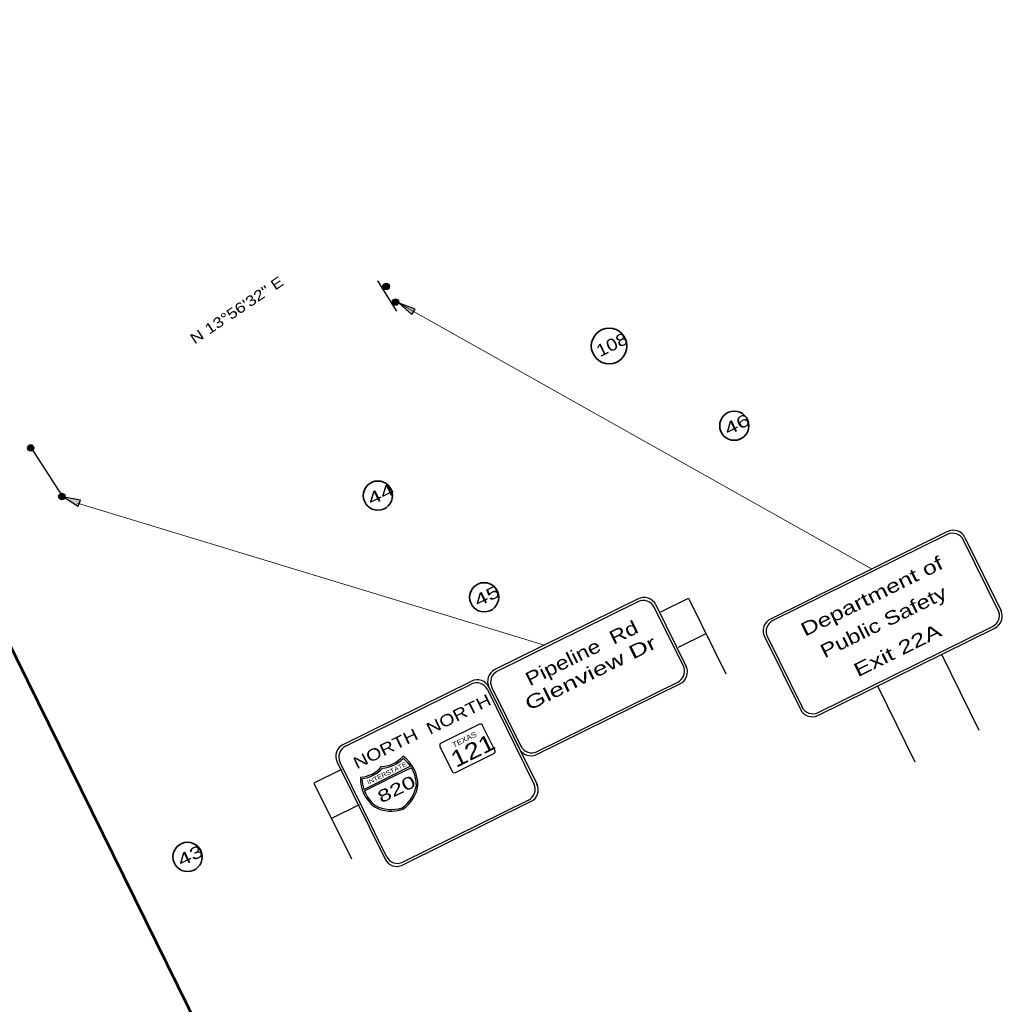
# Model space of a CAD drawing. Extents: x 2356431 to 2371438, y 6972864 to 6982525.
# Drawn here: x 2365828 to 2366960, y 6978894 to 6980028 of the extents above; entities that cross this region are included whole.
import ezdxf
from ezdxf.enums import TextEntityAlignment as Align

# ---------------------------------------------------------------- set-up
doc = ezdxf.new("R2010")
doc.units = 0
doc.header["$LTSCALE"] = 5.6
for name, color, linetype, lineweight in [('1', 7, 'Continuous', 25), ('17', 7, 'Continuous', 35), ('28', 7, 'Continuous', 35)]:
    doc.layers.add(name, color=color, linetype=linetype, lineweight=lineweight)

msp = doc.modelspace()

# ---------------------------------------------------------------- hatches: boundary and pattern name
at = {"layer": '1'}
for points in [[(2366246.217, 6979721.254, 1), (2366253.662, 6979720.728, 1)], [(2366257.128, 6979703.235, 1), (2366264.573, 6979702.71, 1)], [(2366264.891, 6979701.538), (2366279.644, 6979688.739), (2366283.284, 6979694.954)], [(2365843.964, 6979535.242, 1), (2365836.537, 6979534.506, 1)], [(2365880.035, 6979479.344, 1), (2365872.608, 6979478.608, 1)], [(2365878.551, 6979478.108), (2365895.163, 6979467.836), (2365897.761, 6979474.553)]]:
    msp.add_hatch(color=256, dxfattribs=at).paths.add_polyline_path(points)

# ---------------------------------------------------------------- linework, layer by layer
at = {"layer": '1', "lineweight": 53}
msp.add_line((2365274.698, 6980404.566), (2366089.834, 6978752.959), dxfattribs=at)
at = {"layer": '1'}
for p, q in [((2366262.128, 6979692.544), (2366240.48, 6979727.603)), ((2365840.38, 6979535.416), (2365876.764, 6979478.712)), ((2366897.034, 6979438.449), (2366692.9, 6979337.61)), ((2366896.596, 6979435.087), (2366695.833, 6979335.925)), ((2366956.339, 6979345.964), (2366915.485, 6979428.681)), ((2366917.183, 6979431.624), (2366958.818, 6979347.331)), ((2366540.586, 6979360.951), (2366375.359, 6979279.406)), ((2366566.679, 6979346.051), (2366598.565, 6979361.789)), ((2366598.565, 6979361.789), (2366641.672, 6979274.445)), ((2366540.145, 6979357.592), (2366378.29, 6979277.721)), ((2366593.335, 6979281.658), (2366559.029, 6979351.179)), ((2366560.728, 6979354.12), (2366595.814, 6979283.024)), ((2366747.442, 6979226.514), (2366951.569, 6979327.35)), ((2366748.15, 6979230.012), (2366949.078, 6979329.264)), ((2366586.822, 6979305.245), (2366618.706, 6979320.98)), ((2366686.065, 6979317.456), (2366727.421, 6979233.728)), ((2366689.436, 6979317.015), (2366729.423, 6979236.057)), ((2366890.217, 6979297.044), (2366933.354, 6979209.715)), ((2366200.361, 6979192.988), (2366348.439, 6979266.06)), ((2366203.286, 6979191.295), (2366348.003, 6979262.706)), ((2366366.836, 6979256.328), (2366420.392, 6979147.805)), ((2366368.517, 6979259.254), (2366423.904, 6979147.019)), ((2366368.517, 6979259.254), (2366403.324, 6979188.722)), ((2366371.887, 6979258.813), (2366405.327, 6979191.051)), ((2366423.343, 6979181.501), (2366588.559, 6979263.045)), ((2366424.052, 6979184.999), (2366586.07, 6979264.956)), ((2366816.378, 6979260.568), (2366859.515, 6979173.239)), ((2366357.436, 6979216.371), (2366313.275, 6979194.582)), ((2366375.329, 6979186.45), (2366361.199, 6979215.093)), ((2366312.002, 6979190.813), (2366326.13, 6979162.17)), ((2366329.898, 6979160.896), (2366374.056, 6979182.683)), ((2366193.559, 6979172.892), (2366248.771, 6979060.999)), ((2366250.462, 6979063.926), (2366196.897, 6979172.461)), ((2366278.132, 6979167.947), (2366251.233, 6979154.668)), ((2366279.141, 6979166.333), (2366252.071, 6979152.974)), ((2366198.696, 6979164.44), (2366166.811, 6979148.703)), ((2366224.333, 6979141.39), (2366251.233, 6979154.668)), ((2366166.811, 6979148.703), (2366209.918, 6979061.36)), ((2366224.985, 6979139.599), (2366252.071, 6979152.974)), ((2366218.833, 6979123.631), (2366186.95, 6979107.894)), ((2366416.935, 6979127.285), (2366268.856, 6979054.2)), ((2366414.013, 6979128.971), (2366269.296, 6979057.549))]:
    msp.add_line(p, q, dxfattribs=at)
at = {"layer": '1', "lineweight": 13}
for p, q in [((2366264.705, 6979701.53), (2366809.548, 6979395.686)), ((2365894.059, 6979471.262), (2366432.378, 6979307.547))]:
    msp.add_line(p, q, dxfattribs=at)
at = {"layer": '1'}
for points in [[(2366264.891, 6979701.538), (2366279.644, 6979688.739), (2366283.284, 6979694.954)], [(2365878.551, 6979478.108), (2365895.163, 6979467.836), (2365897.761, 6979474.553)]]:
    msp.add_lwpolyline(points, close=True, dxfattribs=at)
for centre in [(2366249.939, 6979720.991), (2366260.85, 6979702.973), (2365840.25, 6979534.874), (2365876.321, 6979478.976)]:
    msp.add_circle(centre, 3.732, dxfattribs=at)
for centre, radius, start, end in [((2366903.697, 6979424.956), 15.049, 26.28789, 117.70539), ((2366902.844, 6979422.436), 14.108, 26.28789, 116.28789), ((2366546.386, 6979344.939), 14.108, 26.26806, 116.26806), ((2366547.24, 6979347.458), 15.049, 26.26806, 117.68557), ((2366945.18, 6979340.976), 15.049, 295.11832, 24.98843), ((2366699.565, 6979324.12), 15.049, 116.28789, 206.28789), ((2366702.085, 6979323.266), 14.108, 116.28789, 206.28789), ((2366942.829, 6979341.912), 14.108, 296.28789, 16.69254), ((2366382.02, 6979265.914), 15.049, 116.26806, 206.26806), ((2366579.824, 6979277.612), 14.108, 296.26806, 16.67271), ((2366582.175, 6979276.675), 15.049, 295.0985, 24.9686), ((2366355.077, 6979252.612), 15.001, 26.26895, 116.26895), ((2366384.539, 6979265.06), 14.108, 116.26806, 206.26806), ((2366354.226, 6979250.101), 14.063, 26.26895, 116.26895), ((2366741.049, 6979240.14), 15.049, 206.28789, 295.11832), ((2366741.902, 6979242.659), 14.108, 206.28789, 296.28789), ((2366358.677, 6979213.846), 2.813, 26.26788, 116.26788), ((2366206.999, 6979179.533), 15.001, 116.26895, 206.26895), ((2366209.511, 6979178.682), 14.063, 116.26895, 206.26895), ((2366314.522, 6979192.054), 2.813, 116.26788, 206.26788), ((2366416.954, 6979195.13), 15.049, 206.26806, 295.0985), ((2366417.809, 6979197.65), 14.108, 206.26806, 296.26806), ((2366242.642, 6979203.589), 35.984, 273.44845, 318.29876), ((2366242.642, 6979203.589), 37.874, 274.64636, 315.6432), ((2366244.75, 6979145.781), 41.954, 0.13125, 53.83362), ((2366244.75, 6979145.781), 40.064, 33.57769, 51.44245), ((2366372.81, 6979185.211), 2.813, 296.26788, 26.26788), ((2366217.613, 6979191.236), 35.984, 274.23736, 319.08768), ((2366217.613, 6979191.236), 37.874, 276.89292, 317.88976), ((2366244.75, 6979145.781), 40.064, 0.34779, 30.85977), ((2366262.215, 6979154.401), 41.954, 178.7025, 232.40488), ((2366262.215, 6979154.401), 40.064, 181.09368, 198.95843), ((2366328.655, 6979163.419), 2.813, 206.26788, 296.26788), ((2366246.51, 6979152.261), 38.808, 304.1061, 350.75248), ((2366246.51, 6979152.261), 40.698, 303.73996, 350.97586), ((2366407.786, 6979141.581), 14.063, 296.26895, 26.26895), ((2366410.298, 6979140.729), 15.001, 296.26895, 26.26895), ((2366262.215, 6979154.401), 40.064, 201.67636, 232.18834), ((2366256.002, 6979156.945), 40.698, 241.56027, 288.79617), ((2366256.002, 6979156.945), 38.808, 241.78364, 288.43003), ((2366263.071, 6979070.162), 14.063, 206.26895, 296.26895), ((2366262.22, 6979067.65), 15.001, 206.26895, 296.26895)]:
    msp.add_arc(centre, radius, start, end, dxfattribs=at)
at = {"layer": '17'}
for centre, radius in [((2366507.03, 6979652.317), 20.576), ((2366651.289, 6979560.49), 16.828), ((2366240.481, 6979479.922), 16.828), ((2366362.988, 6979362.742), 16.828), ((2366021.107, 6979063.542), 16.828)]:
    msp.add_circle(centre, radius, dxfattribs=at)

# ---------------------------------------------------------------- texts
at = {"layer": '1'}
for s, height, rotation, width, p in [('Department of', 15.68, 26.288, 1.35, (2366813.203, 6979356.962)), ('Public Safety', 15.68, 26.288, 1.3, (2366826.549, 6979327.57)), ('Pipeline  Rd', 15.68, 26.268, 1.25, (2366478.82, 6979291.415)), ('Exit 22A', 15.68, 26.288, 1.4, (2366842.799, 6979294.672)), ('Glenview Dr', 15.68, 26.268, 1.45, (2366489.022, 6979268.368)), ('NORTH', 13.5, 26.269, 1.25, (2366336.491, 6979221.87)), ('NORTH', 13.5, 26.269, 1.25, (2366252.267, 6979182.244))]:
    msp.add_text(s, height=height, rotation=rotation, dxfattribs=dict(at, width=width)).set_placement(p, align=Align.CENTER)
for s, height, width, p in [('TEXAS', 6, 1.15, (2366327.911, 6979189.414)), ('121', 18.75, 1.25, (2366330.521, 6979166.116)), ('INTERSTATE', 5.198, 1.15, (2366229.647, 6979146.712)), ('820', 14.18, 1.45, (2366244.442, 6979125.177))]:
    msp.add_text(s, height=height, rotation=26.268, dxfattribs=dict(at, width=width)).set_placement(p)
at = {"layer": '17'}
for s, width, p in [('108', 1.2, (2366513.275, 6979647.593)), ('46', 1.45, (2366657.585, 6979555.792)), ('44', 1.5, (2366246.776, 6979475.223)), ('45', 1.45, (2366369.282, 6979358.042)), ('43', 1.45, (2366027.402, 6979058.843))]:
    msp.add_text(s, height=14, rotation=26.268, dxfattribs=dict(at, width=width)).set_placement(p, align=Align.CENTER)
at = {"layer": '28', "width": 1.25}
msp.add_text('N 13°56\'32" E', height=12, rotation=33.784, dxfattribs=at).set_placement((2366081.149, 6979688.764), align=Align.CENTER)

doc.saveas('drawing.dxf')
